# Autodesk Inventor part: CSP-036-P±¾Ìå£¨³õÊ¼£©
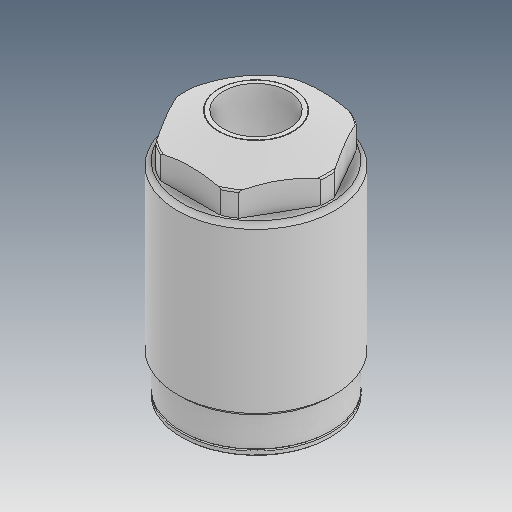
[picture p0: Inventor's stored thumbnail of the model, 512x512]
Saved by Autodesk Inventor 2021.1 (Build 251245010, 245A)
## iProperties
Created: 2019-01
Part Number: CSP-036-P±¾Ìå£¨³õÊ¼£©
Material: Ogólny
Document SubType Name: Modeling
Designer: user
Density: 1 g/cm^3
Appearance: Domyślna
Author: user
Revision Number: ÈÎºÎ
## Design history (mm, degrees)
feature "ÇÐ³ý-À­Éì2"
node "Bryła1"
